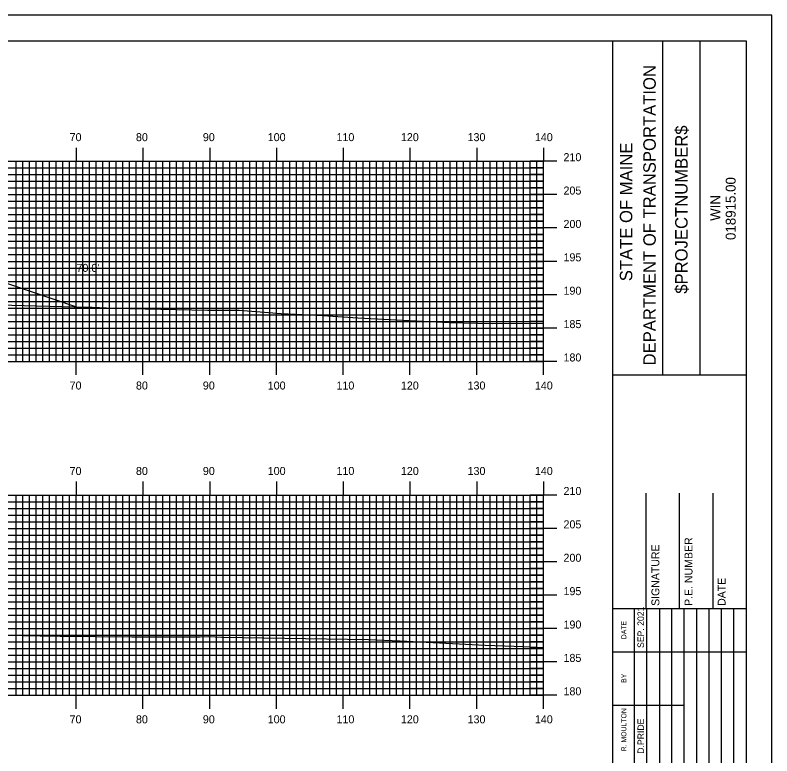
# Model space of a CAD drawing. Extents: x 1807438 to 1807782, y 442591 to 442811.
# Drawn here: x 1807665.1 to 1807778.5, y 442699.6 to 442810.5 of the extents above; entities that cross this region are included whole.
import ezdxf

# ---------------------------------------------------------------- set-up
doc = ezdxf.new("R2010")
doc.units = 0
for name, color, linetype in [('BORDER', 7, 'Continuous'), ('D_Roadway_SlopeLines', 7, 'Continuous'), ('D_Text_Standard', 7, 'Continuous'), ('H_V ANNOTATION', 7, 'Continuous'), ('MAJOR', 7, 'Continuous'), ('MINOR', 7, 'Continuous'), ('PLOT BOUNDARY', 7, 'Continuous'), ('S_Roadway_Centerline', 7, 'Continuous')]:
    doc.layers.add(name, color=color, linetype=linetype)

msp = doc.modelspace()

# ---------------------------------------------------------------- linework, layer by layer
at = {"layer": 'BORDER'}
for p, q in [((1807754.67, 442596.67), (1807754.67, 442806.67)), ((1807762.13, 442756.66), (1807762.13, 442806.66)), ((1807767.72, 442756.66), (1807767.72, 442806.66)), ((1807754.67, 442756.65), (1807774.67, 442756.65)), ((1807759.67, 442721.67), (1807759.67, 442738.97)), ((1807764.67, 442721.67), (1807764.67, 442738.97)), ((1807769.67, 442721.67), (1807769.67, 442738.97)), ((1807754.67, 442721.67), (1807774.67, 442721.67))]:
    msp.add_line(p, q, dxfattribs=at)
msp.add_lwpolyline([(1807454.67, 442596.67), (1807774.67, 442596.67), (1807774.67, 442806.67), (1807454.67, 442806.67)], close=True, dxfattribs=at)
for points in [[(1807757.9, 442715.17), (1807757.9, 442721.67)], [(1807759.77, 442686.68), (1807759.77, 442721.67)], [(1807761.63, 442721.67), (1807761.63, 442686.68)], [(1807763.49, 442686.68), (1807763.49, 442721.67)], [(1807765.36, 442686.68), (1807765.36, 442721.67)], [(1807767.22, 442686.68), (1807767.22, 442721.67)], [(1807769.08, 442686.68), (1807769.08, 442721.67)], [(1807770.95, 442686.68), (1807770.95, 442721.67)], [(1807772.81, 442686.68), (1807772.81, 442721.67)], [(1807757.9, 442686.68), (1807757.9, 442720.26)], [(1807754.67, 442715.17), (1807774.67, 442715.17)], [(1807754.67, 442707.17), (1807757.9, 442707.17)], [(1807757.9, 442707.17), (1807765.36, 442707.17)]]:
    msp.add_lwpolyline(points, dxfattribs=at)
at = {"layer": 'D_Roadway_SlopeLines'}
msp.add_lwpolyline([(1807641.22, 442778.04), (1807644.46, 442776.94), (1807674.31, 442766.84)], dxfattribs=at)
at = {"layer": 'MAJOR'}
for p, q in [((1807674.27, 442790.67), (1807674.27, 442788.67)), ((1807684.27, 442790.67), (1807684.27, 442788.67)), ((1807694.27, 442790.67), (1807694.27, 442788.67)), ((1807704.27, 442790.67), (1807704.27, 442788.67)), ((1807714.27, 442790.67), (1807714.27, 442788.67)), ((1807724.27, 442790.67), (1807724.27, 442788.67)), ((1807734.27, 442790.67), (1807734.27, 442788.67)), ((1807744.27, 442790.67), (1807744.27, 442788.67)), ((1807464.27, 442788.67), (1807744.27, 442788.67)), ((1807464.27, 442788.67), (1807744.27, 442788.67)), ((1807674.27, 442758.67), (1807674.27, 442788.67)), ((1807684.27, 442758.67), (1807684.27, 442788.67)), ((1807694.27, 442758.67), (1807694.27, 442788.67)), ((1807704.27, 442758.67), (1807704.27, 442788.67)), ((1807714.27, 442758.67), (1807714.27, 442788.67)), ((1807724.27, 442758.67), (1807724.27, 442788.67)), ((1807734.27, 442758.67), (1807734.27, 442788.67)), ((1807746.28, 442788.67), (1807742.27, 442788.67)), ((1807744.27, 442758.67), (1807744.27, 442788.67)), ((1807744.27, 442758.67), (1807744.27, 442788.67)), ((1807464.27, 442783.67), (1807744.27, 442783.67)), ((1807746.28, 442783.67), (1807742.27, 442783.67)), ((1807464.27, 442778.67), (1807744.27, 442778.67)), ((1807746.28, 442778.67), (1807742.27, 442778.67)), ((1807464.27, 442773.67), (1807744.27, 442773.67)), ((1807746.28, 442773.67), (1807742.27, 442773.67)), ((1807464.27, 442768.67), (1807744.27, 442768.67)), ((1807746.28, 442768.67), (1807742.27, 442768.67)), ((1807464.27, 442763.67), (1807744.27, 442763.67)), ((1807746.28, 442763.67), (1807742.27, 442763.67)), ((1807464.27, 442758.67), (1807744.27, 442758.67)), ((1807464.27, 442758.67), (1807744.27, 442758.67)), ((1807674.27, 442756.66), (1807674.27, 442758.67)), ((1807684.27, 442756.66), (1807684.27, 442758.67)), ((1807694.27, 442756.66), (1807694.27, 442758.67)), ((1807704.27, 442756.66), (1807704.27, 442758.67)), ((1807714.27, 442756.66), (1807714.27, 442758.67)), ((1807724.27, 442756.66), (1807724.27, 442758.67)), ((1807734.27, 442756.66), (1807734.27, 442758.67)), ((1807746.28, 442758.67), (1807742.27, 442758.67)), ((1807744.27, 442756.66), (1807744.27, 442758.67)), ((1807674.27, 442740.67), (1807674.27, 442738.67)), ((1807684.27, 442740.67), (1807684.27, 442738.67)), ((1807694.27, 442740.67), (1807694.27, 442738.67)), ((1807704.27, 442740.67), (1807704.27, 442738.67)), ((1807714.27, 442740.67), (1807714.27, 442738.67)), ((1807724.27, 442740.67), (1807724.27, 442738.67)), ((1807734.27, 442740.67), (1807734.27, 442738.67)), ((1807744.27, 442740.67), (1807744.27, 442738.67)), ((1807464.27, 442738.67), (1807744.27, 442738.67)), ((1807464.27, 442738.67), (1807744.27, 442738.67)), ((1807674.27, 442708.67), (1807674.27, 442738.67)), ((1807684.27, 442708.67), (1807684.27, 442738.67)), ((1807694.27, 442708.67), (1807694.27, 442738.67)), ((1807704.27, 442708.67), (1807704.27, 442738.67)), ((1807714.27, 442708.67), (1807714.27, 442738.67)), ((1807724.27, 442708.67), (1807724.27, 442738.67)), ((1807734.27, 442708.67), (1807734.27, 442738.67)), ((1807746.28, 442738.67), (1807742.27, 442738.67)), ((1807744.27, 442708.67), (1807744.27, 442738.67)), ((1807744.27, 442708.67), (1807744.27, 442738.67)), ((1807464.27, 442733.67), (1807744.27, 442733.67)), ((1807746.28, 442733.67), (1807742.27, 442733.67)), ((1807464.27, 442728.67), (1807744.27, 442728.67)), ((1807746.28, 442728.67), (1807742.27, 442728.67)), ((1807464.27, 442723.67), (1807744.27, 442723.67)), ((1807746.28, 442723.67), (1807742.27, 442723.67)), ((1807464.27, 442718.67), (1807744.27, 442718.67)), ((1807746.28, 442718.67), (1807742.27, 442718.67)), ((1807464.27, 442713.67), (1807744.27, 442713.67)), ((1807746.28, 442713.67), (1807742.27, 442713.67)), ((1807464.27, 442708.67), (1807744.27, 442708.67)), ((1807464.27, 442708.67), (1807744.27, 442708.67)), ((1807674.27, 442706.66), (1807674.27, 442708.67)), ((1807684.27, 442706.66), (1807684.27, 442708.67)), ((1807694.27, 442706.66), (1807694.27, 442708.67)), ((1807704.27, 442706.66), (1807704.27, 442708.67)), ((1807714.27, 442706.66), (1807714.27, 442708.67)), ((1807724.27, 442706.66), (1807724.27, 442708.67)), ((1807734.27, 442706.66), (1807734.27, 442708.67)), ((1807746.28, 442708.67), (1807742.27, 442708.67)), ((1807744.27, 442706.66), (1807744.27, 442708.67))]:
    msp.add_line(p, q, dxfattribs=at)
at = {"layer": 'MINOR'}
for p, q in [((1807665.27, 442758.67), (1807665.27, 442788.67)), ((1807666.27, 442758.67), (1807666.27, 442788.67)), ((1807667.27, 442758.67), (1807667.27, 442788.67)), ((1807668.27, 442758.67), (1807668.27, 442788.67)), ((1807669.27, 442758.67), (1807669.27, 442788.67)), ((1807670.27, 442758.67), (1807670.27, 442788.67)), ((1807671.27, 442758.67), (1807671.27, 442788.67)), ((1807672.27, 442758.67), (1807672.27, 442788.67)), ((1807673.27, 442758.67), (1807673.27, 442788.67)), ((1807675.27, 442758.67), (1807675.27, 442788.67)), ((1807676.27, 442758.67), (1807676.27, 442788.67)), ((1807677.27, 442758.67), (1807677.27, 442788.67)), ((1807678.27, 442758.67), (1807678.27, 442788.67)), ((1807679.27, 442758.67), (1807679.27, 442788.67)), ((1807680.27, 442758.67), (1807680.27, 442788.67)), ((1807681.27, 442758.67), (1807681.27, 442788.67)), ((1807682.27, 442758.67), (1807682.27, 442788.67)), ((1807683.27, 442758.67), (1807683.27, 442788.67)), ((1807685.27, 442758.67), (1807685.27, 442788.67)), ((1807686.27, 442758.67), (1807686.27, 442788.67)), ((1807687.27, 442758.67), (1807687.27, 442788.67)), ((1807688.27, 442758.67), (1807688.27, 442788.67)), ((1807689.27, 442758.67), (1807689.27, 442788.67)), ((1807690.27, 442758.67), (1807690.27, 442788.67)), ((1807691.27, 442758.67), (1807691.27, 442788.67)), ((1807692.27, 442758.67), (1807692.27, 442788.67)), ((1807693.27, 442758.67), (1807693.27, 442788.67)), ((1807695.27, 442758.67), (1807695.27, 442788.67)), ((1807696.27, 442758.67), (1807696.27, 442788.67)), ((1807697.27, 442758.67), (1807697.27, 442788.67)), ((1807698.27, 442758.67), (1807698.27, 442788.67)), ((1807699.27, 442758.67), (1807699.27, 442788.67)), ((1807700.27, 442758.67), (1807700.27, 442788.67)), ((1807701.27, 442758.67), (1807701.27, 442788.67)), ((1807702.27, 442758.67), (1807702.27, 442788.67)), ((1807703.27, 442758.67), (1807703.27, 442788.67)), ((1807705.27, 442758.67), (1807705.27, 442788.67)), ((1807706.27, 442758.67), (1807706.27, 442788.67)), ((1807707.27, 442758.67), (1807707.27, 442788.67)), ((1807708.27, 442758.67), (1807708.27, 442788.67)), ((1807709.27, 442758.67), (1807709.27, 442788.67)), ((1807710.27, 442758.67), (1807710.27, 442788.67)), ((1807711.27, 442758.67), (1807711.27, 442788.67)), ((1807712.27, 442758.67), (1807712.27, 442788.67)), ((1807713.27, 442758.67), (1807713.27, 442788.67)), ((1807715.27, 442758.67), (1807715.27, 442788.67)), ((1807716.27, 442758.67), (1807716.27, 442788.67)), ((1807717.27, 442758.67), (1807717.27, 442788.67)), ((1807718.27, 442758.67), (1807718.27, 442788.67)), ((1807719.27, 442758.67), (1807719.27, 442788.67)), ((1807720.27, 442758.67), (1807720.27, 442788.67)), ((1807721.27, 442758.67), (1807721.27, 442788.67)), ((1807722.27, 442758.67), (1807722.27, 442788.67)), ((1807723.27, 442758.67), (1807723.27, 442788.67)), ((1807725.27, 442758.67), (1807725.27, 442788.67)), ((1807726.27, 442758.67), (1807726.27, 442788.67)), ((1807727.27, 442758.67), (1807727.27, 442788.67)), ((1807728.27, 442758.67), (1807728.27, 442788.67)), ((1807729.27, 442758.67), (1807729.27, 442788.67)), ((1807730.27, 442758.67), (1807730.27, 442788.67)), ((1807731.27, 442758.67), (1807731.27, 442788.67)), ((1807732.27, 442758.67), (1807732.27, 442788.67)), ((1807733.27, 442758.67), (1807733.27, 442788.67)), ((1807735.27, 442758.67), (1807735.27, 442788.67)), ((1807736.27, 442758.67), (1807736.27, 442788.67)), ((1807737.27, 442758.67), (1807737.27, 442788.67)), ((1807738.27, 442758.67), (1807738.27, 442788.67)), ((1807739.27, 442758.67), (1807739.27, 442788.67)), ((1807740.27, 442758.67), (1807740.27, 442788.67)), ((1807741.27, 442758.67), (1807741.27, 442788.67)), ((1807742.27, 442758.67), (1807742.27, 442788.67)), ((1807743.27, 442758.67), (1807743.27, 442788.67)), ((1807464.27, 442787.67), (1807744.27, 442787.67)), ((1807744.27, 442787.67), (1807742.27, 442787.67)), ((1807464.27, 442786.67), (1807744.27, 442786.67)), ((1807744.27, 442786.67), (1807742.27, 442786.67)), ((1807464.27, 442785.67), (1807744.27, 442785.67)), ((1807744.27, 442785.67), (1807742.27, 442785.67)), ((1807464.27, 442784.67), (1807744.27, 442784.67)), ((1807744.27, 442784.67), (1807742.27, 442784.67)), ((1807464.27, 442782.67), (1807744.27, 442782.67)), ((1807744.27, 442782.67), (1807742.27, 442782.67)), ((1807464.27, 442781.67), (1807744.27, 442781.67)), ((1807464.27, 442780.67), (1807744.27, 442780.67)), ((1807744.27, 442781.67), (1807742.27, 442781.67)), ((1807744.27, 442780.67), (1807742.27, 442780.67)), ((1807464.27, 442779.67), (1807744.27, 442779.67)), ((1807744.27, 442779.67), (1807742.27, 442779.67)), ((1807464.27, 442777.67), (1807744.27, 442777.67)), ((1807744.27, 442777.67), (1807742.27, 442777.67)), ((1807464.27, 442776.67), (1807744.27, 442776.67)), ((1807744.27, 442776.67), (1807742.27, 442776.67)), ((1807464.27, 442775.67), (1807744.27, 442775.67)), ((1807744.27, 442775.67), (1807742.27, 442775.67)), ((1807464.27, 442774.67), (1807744.27, 442774.67)), ((1807744.27, 442774.67), (1807742.27, 442774.67)), ((1807464.27, 442772.67), (1807744.27, 442772.67)), ((1807744.27, 442772.67), (1807742.27, 442772.67)), ((1807464.27, 442771.67), (1807744.27, 442771.67)), ((1807744.27, 442771.67), (1807742.27, 442771.67)), ((1807464.27, 442770.67), (1807744.27, 442770.67)), ((1807744.27, 442770.67), (1807742.27, 442770.67)), ((1807464.27, 442769.67), (1807744.27, 442769.67)), ((1807744.27, 442769.67), (1807742.27, 442769.67)), ((1807464.27, 442767.67), (1807744.27, 442767.67)), ((1807744.27, 442767.67), (1807742.27, 442767.67)), ((1807464.27, 442766.67), (1807744.27, 442766.67)), ((1807744.27, 442766.67), (1807742.27, 442766.67)), ((1807464.27, 442765.67), (1807744.27, 442765.67)), ((1807744.27, 442765.67), (1807742.27, 442765.67)), ((1807464.27, 442764.67), (1807744.27, 442764.67)), ((1807744.27, 442764.67), (1807742.27, 442764.67)), ((1807464.27, 442762.67), (1807744.27, 442762.67)), ((1807744.27, 442762.67), (1807742.27, 442762.67)), ((1807464.27, 442761.67), (1807744.27, 442761.67)), ((1807744.27, 442761.67), (1807742.27, 442761.67)), ((1807464.27, 442760.67), (1807744.27, 442760.67)), ((1807744.27, 442760.67), (1807742.27, 442760.67)), ((1807464.27, 442759.67), (1807744.27, 442759.67)), ((1807744.27, 442759.67), (1807742.27, 442759.67)), ((1807665.27, 442708.67), (1807665.27, 442738.67)), ((1807666.27, 442708.67), (1807666.27, 442738.67)), ((1807667.27, 442708.67), (1807667.27, 442738.67)), ((1807668.27, 442708.67), (1807668.27, 442738.67)), ((1807669.27, 442708.67), (1807669.27, 442738.67)), ((1807670.27, 442708.67), (1807670.27, 442738.67)), ((1807671.27, 442708.67), (1807671.27, 442738.67)), ((1807672.27, 442708.67), (1807672.27, 442738.67)), ((1807673.27, 442708.67), (1807673.27, 442738.67)), ((1807675.27, 442708.67), (1807675.27, 442738.67)), ((1807676.27, 442708.67), (1807676.27, 442738.67)), ((1807677.27, 442708.67), (1807677.27, 442738.67)), ((1807678.27, 442708.67), (1807678.27, 442738.67)), ((1807679.27, 442708.67), (1807679.27, 442738.67)), ((1807680.27, 442708.67), (1807680.27, 442738.67)), ((1807681.27, 442708.67), (1807681.27, 442738.67)), ((1807682.27, 442708.67), (1807682.27, 442738.67)), ((1807683.27, 442708.67), (1807683.27, 442738.67)), ((1807685.27, 442708.67), (1807685.27, 442738.67)), ((1807686.27, 442708.67), (1807686.27, 442738.67)), ((1807687.27, 442708.67), (1807687.27, 442738.67)), ((1807688.27, 442708.67), (1807688.27, 442738.67)), ((1807689.27, 442708.67), (1807689.27, 442738.67)), ((1807690.27, 442708.67), (1807690.27, 442738.67)), ((1807691.27, 442708.67), (1807691.27, 442738.67)), ((1807692.27, 442708.67), (1807692.27, 442738.67)), ((1807693.27, 442708.67), (1807693.27, 442738.67)), ((1807695.27, 442708.67), (1807695.27, 442738.67)), ((1807696.27, 442708.67), (1807696.27, 442738.67)), ((1807697.27, 442708.67), (1807697.27, 442738.67)), ((1807698.27, 442708.67), (1807698.27, 442738.67)), ((1807699.27, 442708.67), (1807699.27, 442738.67)), ((1807700.27, 442708.67), (1807700.27, 442738.67)), ((1807701.27, 442708.67), (1807701.27, 442738.67)), ((1807702.27, 442708.67), (1807702.27, 442738.67)), ((1807703.27, 442708.67), (1807703.27, 442738.67)), ((1807705.27, 442708.67), (1807705.27, 442738.67)), ((1807706.27, 442708.67), (1807706.27, 442738.67)), ((1807707.27, 442708.67), (1807707.27, 442738.67)), ((1807708.27, 442708.67), (1807708.27, 442738.67)), ((1807709.27, 442708.67), (1807709.27, 442738.67)), ((1807710.27, 442708.67), (1807710.27, 442738.67)), ((1807711.27, 442708.67), (1807711.27, 442738.67)), ((1807712.27, 442708.67), (1807712.27, 442738.67)), ((1807713.27, 442708.67), (1807713.27, 442738.67)), ((1807715.27, 442708.67), (1807715.27, 442738.67)), ((1807716.27, 442708.67), (1807716.27, 442738.67)), ((1807717.27, 442708.67), (1807717.27, 442738.67)), ((1807718.27, 442708.67), (1807718.27, 442738.67)), ((1807719.27, 442708.67), (1807719.27, 442738.67)), ((1807720.27, 442708.67), (1807720.27, 442738.67)), ((1807721.27, 442708.67), (1807721.27, 442738.67)), ((1807722.27, 442708.67), (1807722.27, 442738.67)), ((1807723.27, 442708.67), (1807723.27, 442738.67)), ((1807725.27, 442708.67), (1807725.27, 442738.67)), ((1807726.27, 442708.67), (1807726.27, 442738.67)), ((1807727.27, 442708.67), (1807727.27, 442738.67)), ((1807728.27, 442708.67), (1807728.27, 442738.67)), ((1807729.27, 442708.67), (1807729.27, 442738.67)), ((1807730.27, 442708.67), (1807730.27, 442738.67)), ((1807731.27, 442708.67), (1807731.27, 442738.67)), ((1807732.27, 442708.67), (1807732.27, 442738.67)), ((1807733.27, 442708.67), (1807733.27, 442738.67)), ((1807735.27, 442708.67), (1807735.27, 442738.67)), ((1807736.27, 442708.67), (1807736.27, 442738.67)), ((1807737.27, 442708.67), (1807737.27, 442738.67)), ((1807738.27, 442708.67), (1807738.27, 442738.67)), ((1807739.27, 442708.67), (1807739.27, 442738.67)), ((1807740.27, 442708.67), (1807740.27, 442738.67)), ((1807741.27, 442708.67), (1807741.27, 442738.67)), ((1807742.27, 442708.67), (1807742.27, 442738.67)), ((1807743.27, 442708.67), (1807743.27, 442738.67)), ((1807464.27, 442737.67), (1807744.27, 442737.67)), ((1807744.27, 442737.67), (1807742.27, 442737.67)), ((1807464.27, 442736.67), (1807744.27, 442736.67)), ((1807744.27, 442736.67), (1807742.27, 442736.67)), ((1807464.27, 442735.67), (1807744.27, 442735.67)), ((1807744.27, 442735.67), (1807742.27, 442735.67)), ((1807464.27, 442734.67), (1807744.27, 442734.67)), ((1807744.27, 442734.67), (1807742.27, 442734.67)), ((1807464.27, 442732.67), (1807744.27, 442732.67)), ((1807744.27, 442732.67), (1807742.27, 442732.67)), ((1807464.27, 442731.67), (1807744.27, 442731.67)), ((1807744.27, 442731.67), (1807742.27, 442731.67)), ((1807464.27, 442730.67), (1807744.27, 442730.67)), ((1807464.27, 442729.67), (1807744.27, 442729.67)), ((1807744.27, 442730.67), (1807742.27, 442730.67)), ((1807744.27, 442729.67), (1807742.27, 442729.67)), ((1807464.27, 442727.67), (1807744.27, 442727.67)), ((1807744.27, 442727.67), (1807742.27, 442727.67)), ((1807464.27, 442726.67), (1807744.27, 442726.67)), ((1807744.27, 442726.67), (1807742.27, 442726.67)), ((1807464.27, 442725.67), (1807744.27, 442725.67)), ((1807744.27, 442725.67), (1807742.27, 442725.67)), ((1807464.27, 442724.67), (1807744.27, 442724.67)), ((1807744.27, 442724.67), (1807742.27, 442724.67)), ((1807464.27, 442722.67), (1807744.27, 442722.67)), ((1807464.27, 442721.67), (1807744.27, 442721.67)), ((1807744.27, 442722.67), (1807742.27, 442722.67)), ((1807744.27, 442721.67), (1807742.27, 442721.67)), ((1807464.27, 442720.67), (1807744.27, 442720.67)), ((1807744.27, 442720.67), (1807742.27, 442720.67)), ((1807464.27, 442719.67), (1807744.27, 442719.67)), ((1807744.27, 442719.67), (1807742.27, 442719.67)), ((1807464.27, 442717.67), (1807744.27, 442717.67)), ((1807744.27, 442717.67), (1807742.27, 442717.67)), ((1807464.27, 442716.67), (1807744.27, 442716.67)), ((1807744.27, 442716.67), (1807742.27, 442716.67)), ((1807464.27, 442715.67), (1807744.27, 442715.67)), ((1807744.27, 442715.67), (1807742.27, 442715.67)), ((1807464.27, 442714.67), (1807744.27, 442714.67)), ((1807744.27, 442714.67), (1807742.27, 442714.67)), ((1807464.27, 442712.67), (1807744.27, 442712.67)), ((1807744.27, 442712.67), (1807742.27, 442712.67)), ((1807464.27, 442711.67), (1807744.27, 442711.67)), ((1807744.27, 442711.67), (1807742.27, 442711.67)), ((1807464.27, 442710.67), (1807744.27, 442710.67)), ((1807744.27, 442710.67), (1807742.27, 442710.67)), ((1807464.27, 442709.67), (1807744.27, 442709.67)), ((1807744.27, 442709.67), (1807742.27, 442709.67))]:
    msp.add_line(p, q, dxfattribs=at)
at = {"layer": 'PLOT BOUNDARY'}
msp.add_lwpolyline([(1807438.49, 442590.55), (1807778.49, 442590.55), (1807778.49, 442810.55), (1807438.49, 442810.55)], close=True, dxfattribs=at)
at = {"layer": 'S_Roadway_Centerline'}
for points in [[(1807653.36, 442767.39), (1807673.96, 442766.85), (1807676.65, 442766.8), (1807679.89, 442766.65), (1807693.96, 442766.36), (1807698.68, 442766.35), (1807704.99, 442765.84), (1807711.24, 442765.54), (1807716.48, 442765.2), (1807730.12, 442764.5), (1807736.59, 442764.37), (1807744.27, 442764.41)], [(1807651.47, 442717.95), (1807668.87, 442717.56), (1807671.86, 442717.51), (1807682.59, 442717.44), (1807692.82, 442717.44), (1807694.09, 442717.46), (1807696.06, 442717.4), (1807718.05, 442717.04), (1807722.81, 442716.81), (1807735.52, 442716.19), (1807741.31, 442715.99), (1807744.27, 442715.85)]]:
    msp.add_lwpolyline(points, dxfattribs=at)

# ---------------------------------------------------------------- texts
at = {"layer": 'BORDER'}
for s, height, p in [('DEPARTMENT OF TRANSPORTATION', 1.8635, (1807761.09, 442758.08)), ('$PROJECTNUMBER$', 1.8635, (1807765.86, 442768.82)), ('STATE OF MAINE', 1.8635, (1807757.58, 442770.69)), ('018915.00', 1.491, (1807773.06, 442776.86)), ('WIN', 1.491, (1807770.75, 442779.73)), ('P.E. NUMBER', 1.1811, (1807766.59, 442722.06)), ('SIGNATURE', 1.181, (1807761.63, 442722.06)), ('DATE', 1.181, (1807771.55, 442722.06)), ('SEP. 2021', 0.969, (1807759.32, 442715.76)), ('DATE', 0.743, (1807756.68, 442717.08)), ('BY', 0.743, (1807756.68, 442710.54)), ('R. MOULTON', 0.745, (1807756.68, 442700.28)), ('D.PRIDE', 0.969, (1807759.32, 442699.92))]:
    msp.add_text(s, height=height, rotation=90, dxfattribs=at).set_placement(p)
at = {"layer": 'D_Text_Standard'}
msp.add_text("70.0'", height=1.2, dxfattribs=at).set_placement((1807674.31, 442772.09))
at = {"layer": 'H_V ANNOTATION'}
for s, p in [('70', (1807673.28, 442791.67)), ('80', (1807683.22, 442791.67)), ('90', (1807693.24, 442791.67)), ('100', (1807702.96, 442791.67)), ('110', (1807713.26, 442791.67)), ('120', (1807722.91, 442791.67)), ('130', (1807732.9, 442791.67)), ('140', (1807742.98, 442791.67)), ('210', (1807747.27, 442788.67)), ('205', (1807747.27, 442783.67)), ('200', (1807747.27, 442778.67)), ('195', (1807747.27, 442773.67)), ('190', (1807747.27, 442768.67)), ('185', (1807747.27, 442763.67)), ('180', (1807747.27, 442758.67)), ('70', (1807673.28, 442754.47)), ('80', (1807683.22, 442754.47)), ('90', (1807693.24, 442754.47)), ('100', (1807702.96, 442754.47)), ('110', (1807713.26, 442754.47)), ('120', (1807722.91, 442754.47)), ('130', (1807732.9, 442754.47)), ('140', (1807742.98, 442754.47)), ('70', (1807673.28, 442741.67)), ('80', (1807683.22, 442741.67)), ('90', (1807693.24, 442741.67)), ('100', (1807702.96, 442741.67)), ('110', (1807713.26, 442741.67)), ('120', (1807722.91, 442741.67)), ('130', (1807732.9, 442741.67)), ('140', (1807742.98, 442741.67)), ('210', (1807747.27, 442738.67)), ('205', (1807747.27, 442733.67)), ('200', (1807747.27, 442728.67)), ('195', (1807747.27, 442723.67)), ('190', (1807747.27, 442718.67)), ('185', (1807747.27, 442713.67)), ('180', (1807747.27, 442708.67)), ('70', (1807673.28, 442704.47)), ('80', (1807683.22, 442704.47)), ('90', (1807693.24, 442704.47)), ('100', (1807702.96, 442704.47)), ('110', (1807713.26, 442704.47)), ('120', (1807722.91, 442704.47)), ('130', (1807732.9, 442704.47)), ('140', (1807742.98, 442704.47))]:
    msp.add_text(s, height=1.2, dxfattribs=at).set_placement(p)

doc.saveas('drawing.dxf')
